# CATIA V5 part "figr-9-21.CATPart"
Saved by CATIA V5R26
Part number: Part3
Bounding box of the stored display mesh (mm): x -112 to 0, y -101.683 to 104.654, z -80.304 to 44.557
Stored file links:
  D:\_Deepak\CATIA\CATIA V5-6R2016_Deepak\Resources\Part files\Partfiles\c09_catia_v5_6r2016_prt\figr-9-21.CATPart
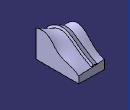
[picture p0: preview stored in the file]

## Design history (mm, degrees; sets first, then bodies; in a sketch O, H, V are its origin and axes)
Set1
  Plane1: type Offset, RefPlane yz-plane, Offset -112
  Plane2: type Offset, RefPlane yz-plane, Offset -63
  Plane3: type Normal, Curve Sketch4, RefPoint vertex of Sketch4
Body1 (main body)
  Sketch1 on yz-plane, origin (0, 0, 0), H (0, 1, 0), V (0, 0, 1)
    spline S1 through (-92.6897, 40.1119) (-30, 30) (10, -10) (60, -30) (97.3103, -50.3041)
    line L1 (97.3103, -50.3041) -> (97.3103, -80.3041)
    line L2 (97.3103, -80.3041) -> (-92.6897, -80.3041)
    line L3 (-92.6897, -80.3041) -> (-92.6897, 40.1119)
    point P3 (-92.6897, 40.1119)
    point P4 (97.3103, -50.3041)
    point P5 (-92.6897, 40.1119)
    point P6 (97.3103, -50.3041)
    vertical: L1 V, L3 V
    horizontal: L2 H
    coincidence: P5 P3, P6 P4
  Sketch2 on Plane1, origin (-112, 0, 0), H (0, 1, 0), V (0, 0, 1)
    spline S1 through (-90, -30) (-70, 10) (-20, 40) (40, 0) (100, -40)
    line L1 (100, -40) -> (100, -80)
    line L2 (100, -80) -> (-90, -80)
    line L3 (-90, -80) -> (-90, -30)
    point P3 (-90, -30)
    point P4 (100, -40)
    point P5 (40, 0)
    point P6 (-90, -30)
    point P7 (100, -40)
    coincidence: P5 H, P6 P3, P7 P4
    vertical: L1 V, L3 V
    horizontal: L2 H
  Loft1: Sections (Sketch1; Sketch2)
  Sketch3 on Plane3, origin (0, -40.1726, -44.9298), H (1, 0, 0), V (0, -0.7455, 0.6665)
    point P1 (-63, 68.4187)
    line L1 (-63, 68.4187) -> (-75.2117, 62.4925)
    line L2 (-75.2117, 62.4925) -> (-79.6266, 71.5898)
    line L3 (-79.6266, 71.5898) -> (-57.1205, 82.5119)
    line L4 (-57.1205, 82.5119) -> (-52.7056, 73.4145)
    point P5 (-52.7056, 73.4145)
    line L5 (-52.7056, 73.4145) -> (-63, 68.4187)
    reference projected point E1 (-63, 68.4187) from vertex of Sketch4
    perpendicularity: L2 L1
    parallelism: L3 L1, L4 L2, L5 L1
    coincidence: P5 L1, P1 E1
  Sketch4 on Plane2, origin (-63, 0, 0), H (0, 1, 0), V (0, 0, 1)
    intersected curve E1 from face of Loft1
  Rib1: profile Sketch3, centre curve Sketch4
